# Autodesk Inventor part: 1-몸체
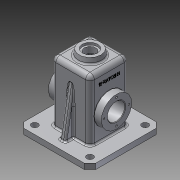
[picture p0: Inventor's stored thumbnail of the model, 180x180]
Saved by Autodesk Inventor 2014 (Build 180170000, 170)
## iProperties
Created: 2016-02
Part Number: 1-몸체
Material: 알루미늄 6061
Document SubType Name: Modeling
Designer: Administrator
Density: 2.71 g/cm^3
Appearance: 알루미늄 - 평지
Mass: 938.875 g
Surface Area: 1044.27 cm^2
Volume: 346.448 cm^3
Author: Administrator
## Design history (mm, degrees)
sketch "스케치1"
  geometry: L1 (65, -65)-(-65, -65); L2 (-65, -65)-(-65, 65); L3 (-65, 65)-(65, 65); L4 (65, 65)-(65, -65); L5 (65, -65)-(-65, 65); L6 (-65, -65)-(65, 65); 1 further point
  constraints: 12 end point, 2 midpoint, 2 parallel, 1 horizontal, 1 perpendicular
  dimensions: "d0" = 130 distance of L2.end L3.end; "d1" = 130 distance of L1.end L2.end
extrude "돌출1" new body sketch "스케치1" distance "d2" = 10; taper "d3" = 0 deg
sketch "스케치2"
  geometry: L1 (35, -35)-(-35, -35); L2 (-35, -35)-(-35, 35); L3 (-35, 35)-(35, 35); L4 (35, 35)-(35, -35); L5 (35, -35)-(-35, 35); L6 (-35, -35)-(35, 35); 1 further point
  constraints: 12 end point, 2 midpoint, 2 parallel, 1 horizontal, 1 perpendicular
  dimensions: "d4" = 70 distance of L1.end L2.end; "d5" = 70 distance of L2.end L3.end
extrude "돌출2" join sketch "스케치2" distance "d6" = 110; taper "d7" = 0 deg
feature "쉘1" dims "d9" = 10, "d10" = 5
fillet "모깎기3" dims "d54" = 8
fillet "모깎기4" dims "d55" = 8
fillet "모깎기5" dims "d56" = 3
fillet "모깎기6" dims "d57" = 3
node "작업 평면1"
sketch "스케치3"
  geometry: C1 r 20 at (0, 0); 1 further point
  constraints: 1 centre point, 1 coincident
  dimensions: "d12" = 40 diameter of C1
extrude "돌출3" join sketch "스케치3" stored distance "d13" = 110; taper "d14" = 10 deg
hole "구멍3" diameter "d46" = 21; stored, may be unused: countersink angle "d50" = 90 deg, drill point angle "d52" = 118 deg; dims "d44" = 10, "d45" = 10, "d47" = 32, "d48" = 28, "d49" = 4, "d51" = 10
sketch "스케치7"
  geometry: L1 (0, 27)-(55, 27); C1 r 27.5 at (55, 27)
  constraints: 2 end point, 1 centre point, 1 coincident, 1 horizontal
  dimensions: "d58" = 55 distance of L1.start L1.end; "d59" = 55 diameter of C1
extrude "돌출6" join sketch "스케치7" distance "d60" = 7; taper "d61" = 0 deg
sketch "스케치8"
  geometry: C1 r 27.5 at (-45, 27); A1 r 27.5 centre (-45, 27) between (-39.78, 0) and (-39.78, 54) reference; 1 further point
  constraints: 1 centre point, 1 coincident
  dimensions: "d62" = 55 diameter of C1
extrude "돌출7" join sketch "스케치8" distance "d63" = 13; taper "d64" = 0 deg
sketch "스케치9"
  geometry: L1 (0, 0)-(-22.5, 0); C1 r 27.5 at (0, 0) reference; 1 further point
  constraints: 2 end point, 1 horizontal
  dimensions: "d65" = 22.5 distance of L1.start L1.end
hole "구멍4" sketch "스케치9" at (-22.5, 0) diameter "d66" = 3.242; stored, may be unused: countersink angle "d70" = 90 deg, drill point angle "d72" = 118 deg; dims "d67" = 8, "d68" = 28, "d69" = 4, "d71" = 10
feature "면 기울기3" dims angle "d76" = 45 deg
feature "면 기울기4" dims angle "d77" = 45 deg
hole "구멍5" diameter "d80" = 32; stored, may be unused: countersink angle "d84" = 90 deg, drill point angle "d86" = 118 deg; dims "d78" = 10, "d79" = 10, "d81" = 8, "d82" = 28, "d83" = 4, "d85" = 10
sketch "스케치10"
  geometry: L1 (-65, 10)-(65, 10) reference; L2 (-35, 112)-(-35, 10) reference; L3 (-50, 10)-(-35, 95.069); L4 (-65, 0)-(-65, 10) reference; 1 further point
  constraints: 2 end point, 2 point on line
  dimensions: "d87" = 15 distance from line of L3.start L4; "d88" = 10 deg angle of L3 L4
feature "리브1" sketch "스케치10" dims "d89" = 1, "d90" = 10, "d91" = 0, "d92" = 0, "d93" = 1, "d94" = 1
sketch "스케치11"
  geometry: L1 (-50, -50)-(50, -50); L2 (50, -50)-(50, 50); L3 (50, 50)-(-50, 50); L4 (-50, 50)-(-50, -50); 3 further points
  constraints: 8 end point, 2 midpoint, 2 parallel, 1 horizontal, 1 horizontal alignment, 1 perpendicular, 1 vertical alignment
  dimensions: "d95" = 100 distance of L3.end L1.start; "d96" = 100 distance of L2.end L3.end
hole "구멍6" sketch "스케치11" at (-50, -50), (50, 50), (50, -50), (-50, 50) diameter "d97" = 12; stored, may be unused: countersink angle "d101" = 90 deg, drill point angle "d103" = 118 deg; dims "d98" = 8, "d99" = 28, "d100" = 4, "d102" = 10
chamfer "모따기1" distance "d104" = 10; stored, may be unused: second distance "d105" = 2, angle "d106" = 45 deg
fillet "모깎기7" dims "d107" = 0.5
fillet "모깎기8" dims "d108" = 0.5
fillet "모깎기9" dims "d109" = 0.5
chamfer "모따기2" distance "d110" = 1; stored, may be unused: second distance "d111" = 2, angle "d112" = 45 deg
fillet "모깎기10" dims "d113" = 3
fillet "모깎기11" dims "d114" = 3
fillet "모깎기12" dims "d115" = 3
fillet "모깎기13" dims "d116" = 3
sketch "스케치12"
  geometry: L1 (-18, 47)-(-18, 7) reference; L2 (99, 62)-(0, 62) reference; 2 further points
  constraints: 1 other
  dimensions: "d117" = 30 distance from line of point (12, 27) L1; "d118" = 35 distance from line of L2 point (12, 27)
feature "엠보싱1" sketch "스케치12" dims "d119" = 0.5, "d120" = 0
node "솔리드1"
pattern_circular "원형 패턴2" dims angle "d74" = 360 deg
mirror "대칭2"
mirror "대칭3"
